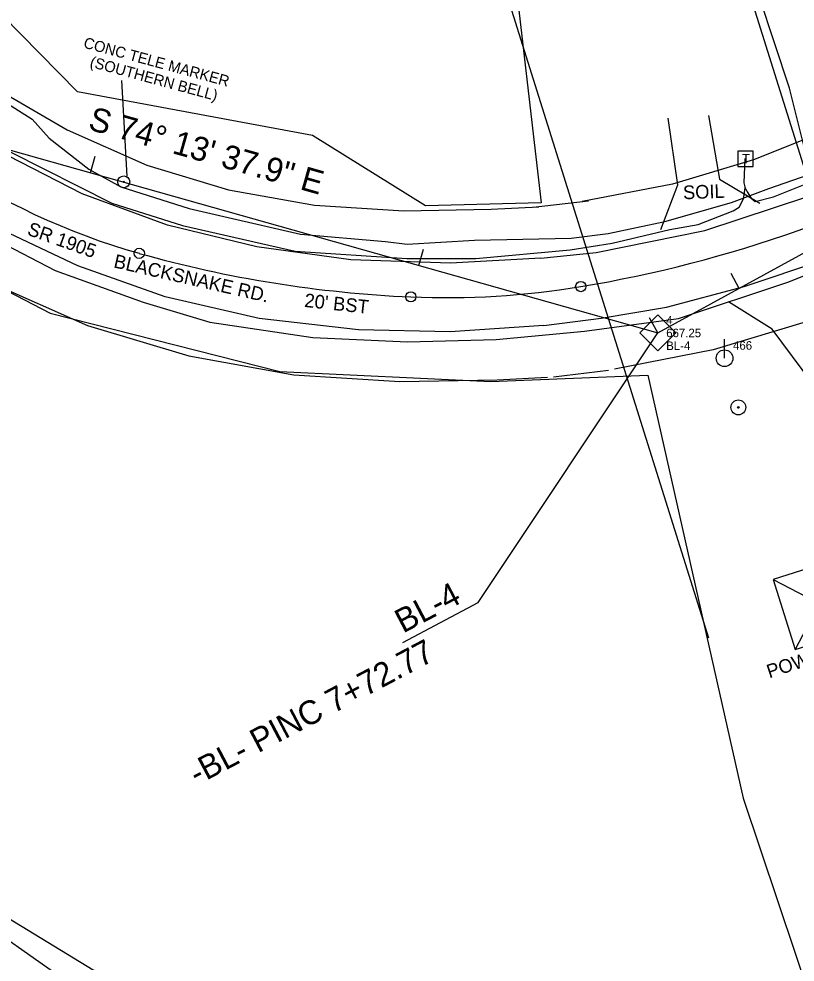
# Model space of a CAD drawing. Extents: x 1380524 to 1382335, y 594765 to 596944.
# Drawn here: x 1381338.3 to 1381565.9, y 595253.4 to 595529.8 of the extents above; entities that cross this region are included whole.
import ezdxf

# ---------------------------------------------------------------- set-up
doc = ezdxf.new("R2010")
doc.units = 0
for name, color, linetype in [('CTL Supplemental Horizontal and Vertical Cogo Comment', 7, 'Continuous'), ('CTL Supplemental Horizontal and Vertical Cogo Elevation', 7, 'Continuous'), ('DTM Contours Major', 7, 'Continuous'), ('Exist Horizontal Alignment', 7, 'Continuous'), ('Exist Horizontal Alignment Station Label', 7, 'Continuous'), ('Exist Horizontal Baseline Alignment', 7, 'Continuous'), ('Exist Horizontal Baseline Alignment Direction Label', 7, 'Continuous'), ('Exist Horizontal Baseline Alignment Station Label', 7, 'Continuous'), ('Exist Horizontal Baseline Alignment Tick small', 7, 'Continuous'), ('Exist Hydro Jurisdictional Stream or Body of Water', 7, 'Continuous'), ('Exist Other Culture Fence Line', 7, 'Continuous'), ('Exist Roads EOP', 7, 'Continuous'), ('Exist Roads EOP Other', 7, 'Continuous'), ('Exist Roads Soil', 7, 'Continuous'), ('Exist Utilities Gas UG Line SUE', 7, 'Continuous'), ('Exist Utilities Other Located Object Leader', 7, 'Continuous'), ('Exist Utilities Telephone Pedestal CELL', 7, 'Continuous'), ('Exist Utilities Telephone UG Cable', 7, 'Continuous'), ('Exist Vegetation Tree CELL', 7, 'Continuous'), ('Exist Vertical Profile Vertical Axis Label', 7, 'Continuous'), ('Prop Drainage Structure Pipe Elbow CELL', 7, 'Continuous'), ('Prop Earthen Structure Cut Ditch Special Detail CELL', 7, 'Continuous'), ('Prop Earthen Structure Cut Ditch Special Detail Label', 7, 'Continuous'), ('Prop Earthen Structure Ditch Flow Line', 7, 'Continuous'), ('Prop Horizontal Alignment Tick Large', 7, 'Continuous'), ('Prop Horizontal Alignment Tick Small', 7, 'Continuous'), ('Prop SS Cut Line', 7, 'Continuous'), ('Prop SS Fill Line', 7, 'Continuous'), ('Scratch_Level_6', 7, 'Continuous')]:
    doc.layers.add(name, color=color, linetype=linetype)

# ---------------------------------------------------------------- blocks, each defined once
blk = doc.blocks.new('EXIST UTILITIES OTHER LOCATED OBJECT')
at = {"layer": 'Prop Earthen Structure Cut Ditch Special Detail CELL'}
for radius in [0.0436, 0.0048]:
    blk.add_circle((0, 0), radius, dxfattribs=at)
blk = doc.blocks.new('EXIST UTILITIES POWER POLE')
at = {"layer": 'Exist Other Culture Fence Line'}
for q in [(0, 0.1125), (0, 0)]:
    blk.add_line((0, 0), q, dxfattribs=at)
blk.add_circle((0, 0), 0.049, dxfattribs=at)
blk = doc.blocks.new('EXIST UTILITIES TELEPHONE PEDESTAL')
at = {"layer": 'Exist Utilities Telephone Pedestal CELL'}
blk.add_line((0, 0), (0, 0), dxfattribs=at)
blk.add_lwpolyline([(-0.0545, -0.0565), (0.0574, -0.0565), (0.0574, 0.0554), (-0.0545, 0.0554), (-0.0545, -0.0565)], dxfattribs=at)
blk.add_text('T', height=0.0684, dxfattribs=at).set_placement((-0.0226, -0.0343))

msp = doc.modelspace()

# ---------------------------------------------------------------- linework, layer by layer
at = {"layer": 'DTM Contours Major'}
msp.add_lwpolyline([(1381559.46, 595365.58), (1381565.93, 595345.03), (1381586.48, 595351.5), (1381580.02, 595372.05), (1381559.46, 595365.58), (1381586.48, 595351.5), (1381580.02, 595372.05), (1381565.93, 595345.03)], dxfattribs=at)
at = {"layer": 'Exist Horizontal Alignment'}
for centre, radius, start, end in [((1381427.83, 595653.65), 200, 216.8315, 254.276), ((1381427.83, 595653.65), 200, 216.8315, 254.276), ((1381427.83, 595653.65), 200, 216.8315, 254.276), ((1381441.55, 595821.31), 375, 279.4361, 299.5612), ((1381441.55, 595821.31), 375, 279.4361, 299.5612), ((1381441.55, 595821.31), 375, 279.4361, 299.5612), ((1381468.48, 595798.03), 350, 254.276, 267.4994), ((1381468.48, 595798.03), 350, 254.276, 267.4994), ((1381468.48, 595798.03), 350, 254.276, 267.4994), ((1381463.68, 595688.14), 240, 267.4994, 279.4361), ((1381463.68, 595688.14), 240, 267.4994, 279.4361), ((1381463.68, 595688.14), 240, 267.4994, 279.4361)]:
    msp.add_arc(centre, radius, start, end, dxfattribs=at)
at = {"layer": 'Exist Horizontal Alignment Station Label'}
for centre in [(1381373.63, 595461.13), (1381503.03, 595451.39), (1381453.21, 595448.37)]:
    msp.add_circle(centre, 1.5, dxfattribs=at)
at = {"layer": 'Exist Horizontal Baseline Alignment'}
for p, q in [((1381525.59, 595437.8), (1381849.7, 595615.17)), ((1381263.09, 595511.95), (1381525.59, 595437.8))]:
    msp.add_line(p, q, dxfattribs=at)
at = {"layer": 'Exist Horizontal Baseline Alignment Station Label'}
for p, q in [((1381472.98, 595358.76), (1381525.59, 595437.8)), ((1381450.88, 595347.11), (1381472.98, 595358.76))]:
    msp.add_line(p, q, dxfattribs=at)
at = {"layer": 'Exist Horizontal Baseline Alignment Tick small'}
for p, q in [((1381359.33, 595484.76), (1381360.68, 595489.57)), ((1381455.56, 595457.58), (1381456.92, 595462.39)), ((1381549.48, 595450.87), (1381547.08, 595455.26)), ((1381525.59, 595437.8), (1381523.19, 595442.19))]:
    msp.add_line(p, q, dxfattribs=at)
at = {"layer": 'Exist Hydro Jurisdictional Stream or Body of Water'}
msp.add_lwpolyline([(1380985.02, 595366.88), (1381014.08, 595367.37), (1381042.38, 595363.3), (1381053.08, 595379.87), (1381083.61, 595386.57), (1381110.12, 595387.98), (1381133.86, 595373.94), (1381147.55, 595358.23), (1381189.33, 595341.18), (1381225.05, 595327.29), (1381256.58, 595311.26), (1381295.63, 595280.09), (1381330.47, 595263.19), (1381357.79, 595244.04), (1381403.48, 595232.23), (1381443.85, 595221.49), (1381471.36, 595213.42), (1381497.44, 595202.53)], dxfattribs=at)
at = {"layer": 'Exist Other Culture Fence Line'}
for q in [(1381545.19, 595436), (1381545.19, 595430.38)]:
    msp.add_line((1381545.19, 595430.38), q, dxfattribs=at)
msp.add_circle((1381545.19, 595430.38), 2.45, dxfattribs=at)
at = {"layer": 'Exist Roads EOP'}
for p, q in [((1381489.07, 595474.63), (1381505.26, 595476.56)), ((1381495, 595424.98), (1381511.19, 595426.92))]:
    msp.add_line(p, q, dxfattribs=at)
for points in [[(1381605.45, 595368.7), (1381418.22, 595965.25)], [(1381540.57, 595348.34), (1381353.34, 595944.89)], [(1381161.15, 595696), (1381164.06, 595686.12), (1381174.18, 595656.96), (1381185.71, 595627.95), (1381196.46, 595603.62), (1381208.77, 595578.34), (1381225.25, 595550.12), (1381243.05, 595524.53), (1381259.54, 595504.93), (1381280.57, 595484.48), (1381303.91, 595467.71), (1381329.76, 595452.68), (1381358.42, 595440), (1381388.14, 595431.06), (1381418.93, 595425.53), (1381449.98, 595423.57), (1381478.51, 595424.07), (1381493.32, 595424.85)], [(1381231.86, 595647.22), (1381241.81, 595624.69), (1381252.89, 595601.94), (1381267.43, 595577.05), (1381282.78, 595554.97), (1381296.18, 595539.04), (1381312.76, 595522.92), (1381331.13, 595509.71), (1381352.52, 595497.29), (1381375.81, 595486.97), (1381399.82, 595479.76), (1381424.98, 595475.23), (1381451.15, 595473.58), (1381476.8, 595474.04), (1381490.75, 595474.77)], [(1381633.23, 595526.86), (1381602.66, 595510.2), (1381576.4, 595497.62), (1381553.64, 595488.58), (1381529.89, 595481.4), (1381503.48, 595476.28)], [(1381657.14, 595482.97), (1381625.41, 595465.67), (1381596.39, 595451.78), (1381570.08, 595441.33), (1381541.87, 595432.81), (1381512.97, 595427.2)]]:
    msp.add_lwpolyline(points, dxfattribs=at)
at = {"layer": 'Exist Utilities Gas UG Line SUE'}
for p, q in [((1381564.26, 595509.53), (1381551.57, 595547.78)), ((1381571.71, 595479.42), (1381564.26, 595509.53))]:
    msp.add_line(p, q, dxfattribs=at)
at = {"layer": 'Exist Utilities Other Located Object Leader'}
msp.add_lwpolyline([(1381370.09, 595483.78), (1381368.47, 595511.8)], dxfattribs=at)
at = {"layer": 'Exist Utilities Telephone UG Cable'}
for p, q in [((1381324.33, 595511.79), (1381342.18, 595500.41)), ((1381342.18, 595500.41), (1381347.23, 595494.85)), ((1381347.23, 595494.85), (1381358.88, 595485.76)), ((1381335.74, 595490.85), (1381365.58, 595475.87)), ((1381550.94, 595481.8), (1381551.27, 595488.88)), ((1381358.88, 595485.76), (1381368.17, 595480.64)), ((1381558.21, 595480.11), (1381574.25, 595485.72)), ((1381551.27, 595480.59), (1381550.94, 595481.8)), ((1381559.54, 595477.68), (1381575.09, 595483.9)), ((1381368.17, 595480.64), (1381388.23, 595474.25)), ((1381547.2, 595476.01), (1381558.21, 595480.11)), ((1381550.74, 595477.08), (1381551.04, 595478.95)), ((1381551.04, 595478.95), (1381551.25, 595480.3)), ((1381551.25, 595480.3), (1381551.27, 595480.59)), ((1381551.25, 595480.3), (1381551.77, 595479.17)), ((1381551.77, 595479.17), (1381552.98, 595477.31)), ((1381527.68, 595470.49), (1381547.2, 595476.01)), ((1381549.5, 595474.7), (1381550.74, 595477.08)), ((1381552.98, 595477.31), (1381554.2, 595476.36)), ((1381554.2, 595476.36), (1381559.54, 595477.68)), ((1381365.58, 595475.87), (1381386.27, 595469.29)), ((1381388.23, 595474.25), (1381420.9, 595466.75)), ((1381537.47, 595469.61), (1381547.7, 595473.6)), ((1381547.7, 595473.6), (1381549.5, 595474.7)), ((1381511.03, 595466.91), (1381527.68, 595470.49)), ((1381324.11, 595469), (1381348.99, 595456.07)), ((1381386.27, 595469.29), (1381419.31, 595461.77)), ((1381512.25, 595464.09), (1381529.1, 595468.14)), ((1381529.1, 595468.14), (1381537.47, 595469.61)), ((1381420.9, 595466.75), (1381445.84, 595464.64)), ((1381452.13, 595463.78), (1381471.89, 595464.99)), ((1381471.89, 595464.99), (1381500.22, 595465.55)), ((1381500.22, 595465.55), (1381511.03, 595466.91)), ((1381445.84, 595464.64), (1381452.13, 595463.78)), ((1381499.91, 595462.15), (1381512.25, 595464.09)), ((1381419.31, 595461.77), (1381452.09, 595459.62)), ((1381452.09, 595459.62), (1381472.24, 595459.64)), ((1381472.24, 595459.64), (1381499.91, 595462.15)), ((1381564.06, 595452.79), (1381583.47, 595460.69)), ((1381348.99, 595456.07), (1381374.72, 595446.83)), ((1381531.69, 595442.05), (1381564.06, 595452.79)), ((1381374.72, 595446.83), (1381394.34, 595440.97)), ((1381394.34, 595440.97), (1381424.51, 595436.48)), ((1381504.1, 595438.32), (1381531.69, 595442.05)), ((1381478.25, 595435.91), (1381504.1, 595438.32)), ((1381424.51, 595436.48), (1381452.23, 595435.15)), ((1381452.23, 595435.15), (1381478.25, 595435.91))]:
    msp.add_line(p, q, dxfattribs=at)
at = {"layer": 'Prop Drainage Structure Pipe Elbow CELL'}
for points in [[(1381540.51, 595501.51), (1381543.66, 595482.82), (1381555.53, 595475.79)], [(1381526.48, 595468.13), (1381531.53, 595481.16), (1381528.67, 595500.75)], [(1381573.88, 595419.06), (1381559.15, 595438.88), (1381546.39, 595446.88)]]:
    msp.add_lwpolyline(points, dxfattribs=at)
at = {"layer": 'Prop Earthen Structure Cut Ditch Special Detail Label'}
for points in [[(1381311.01, 595552.25), (1381321.59, 595588.1), (1381354.11, 595565.54), (1381373.79, 595564.89), (1381382.69, 595595.08), (1381416.12, 595616.7), (1381418.47, 595677.64), (1381445.54, 595666.13), (1381483.46, 595545.08), (1381491.42, 595475.89), (1381457.51, 595475.03), (1381424.36, 595495.63), (1381355.51, 595508.44), (1381311.33, 595553.4)], [(1380970.1, 595427.87), (1381024.06, 595422.83), (1381114.96, 595446.92), (1381185.45, 595457.03), (1381261.8, 595488.06), (1381347.51, 595443.64), (1381414.83, 595426.48), (1381476.71, 595423.61), (1381522.74, 595425.41), (1381550.61, 595301.49), (1381576.12, 595225.45)], [(1381503.34, 595209.65), (1381437.89, 595231.26), (1381360.06, 595251.07), (1381310.4, 595281.34), (1381254.74, 595324.36), (1381199.97, 595347.63), (1381147.52, 595370.02), (1381108.16, 595398.49), (1381050.18, 595388.66), (1381033.41, 595371.94), (1380985.64, 595374.68)]]:
    msp.add_lwpolyline(points, dxfattribs=at)
at = {"layer": 'Prop Earthen Structure Ditch Flow Line'}
for p, q in [((1381491.33, 595459.68), (1381507.54, 595461.4)), ((1381492.25, 595440), (1381509.05, 595442.1))]:
    msp.add_line(p, q, dxfattribs=at)
for points in [[(1381491.33, 595459.68), (1381464.85, 595458.25), (1381435.67, 595459.27), (1381408.13, 595463.04), (1381381.89, 595469.34), (1381356.9, 595478.55), (1381331.5, 595491.59), (1381306.2, 595509.27), (1381284.93, 595529.02), (1381267.78, 595549.61), (1381247.25, 595580.06), (1381224.31, 595624.91), (1381211.16, 595655.93), (1381195.13, 595701.47), (1381187.72, 595727.78)], [(1381492.25, 595440), (1381464.79, 595438.13), (1381437.85, 595438.71), (1381408.74, 595442.02), (1381381.18, 595448.34), (1381355.66, 595457.45), (1381331.8, 595468.68), (1381308.83, 595482.8), (1381287.93, 595499.23), (1381269.66, 595517.22), (1381252.13, 595539.26), (1381236.19, 595562.85), (1381220.35, 595591.19), (1381206.28, 595620.98), (1381194.7, 595648.28), (1381177.83, 595693.24), (1381172.27, 595703.71), (1381163.83, 595709.25)], [(1381507.54, 595461.4), (1381539.44, 595467.79), (1381569.9, 595477.86), (1381604.03, 595493.18), (1381642.92, 595514.12)], [(1381509.05, 595442.1), (1381528.14, 595445.39), (1381550.94, 595451.4), (1381574.04, 595459.16), (1381596.63, 595468.8), (1381619.48, 595480.29), (1381651.75, 595498.4)]]:
    msp.add_lwpolyline(points, dxfattribs=at)
at = {"layer": 'Prop SS Cut Line'}
msp.add_line((1381525.59, 595437.8), (1381525.59, 595437.8), dxfattribs=at)
msp.add_lwpolyline([(1381520.38, 595437.82), (1381525.62, 595443.06), (1381530.87, 595437.81), (1381525.63, 595432.57)], close=True, dxfattribs=at)

# ---------------------------------------------------------------- block references
at = {"layer": 'Exist Other Culture Fence Line', "xscale": 50, "yscale": 50}
msp.add_blockref('EXIST UTILITIES POWER POLE', (1381545.19, 595430.38), dxfattribs=at)
at = {"layer": 'Exist Utilities Telephone Pedestal CELL', "xscale": 40, "yscale": 40}
msp.add_blockref('EXIST UTILITIES TELEPHONE PEDESTAL', (1381551.27, 595488.88), dxfattribs=at)
at = {"layer": 'Prop Earthen Structure Cut Ditch Special Detail CELL'}
for p, xscale, yscale in [((1381369.08, 595482.09), 40, 40), ((1381549.22, 595415.97), 50, 50)]:
    msp.add_blockref('EXIST UTILITIES OTHER LOCATED OBJECT', p, dxfattribs=dict(at, xscale=xscale, yscale=yscale))

# ---------------------------------------------------------------- texts
at = {"layer": 'CTL Supplemental Horizontal and Vertical Cogo Comment'}
msp.add_text('BL-4', height=2.5, dxfattribs=at).set_placement((1381528.09, 595432.8))
at = {"layer": 'CTL Supplemental Horizontal and Vertical Cogo Elevation'}
msp.add_text('667.25', height=2.5, dxfattribs=at).set_placement((1381528.09, 595436.55))
at = {"layer": 'Exist Horizontal Baseline Alignment Direction Label'}
msp.add_text('S 74%%d 13\' 37.9" E', height=7, rotation=344.2272, dxfattribs=at).set_placement((1381358.33, 595497.51))
at = {"layer": 'Exist Horizontal Baseline Alignment Station Label'}
msp.add_text('BL-4', height=7, rotation=27.7977, dxfattribs=at).set_placement((1381450.94, 595349.66))
at = {"layer": 'Exist Roads EOP Other'}
msp.add_text("20' BST", height=4, rotation=353.8056, dxfattribs=at).set_placement((1381421.88, 595445.44))
at = {"layer": 'Exist Roads Soil'}
msp.add_text('4', height=2.5, dxfattribs=at).set_placement((1381528.09, 595440.3))
at = {"layer": 'Exist Vegetation Tree CELL'}
msp.add_text('466', height=2.5, dxfattribs=at).set_placement((1381547.69, 595432.88))
msp.add_text('466', height=2.5, dxfattribs=at).set_placement((1381547.69, 595432.88))
at = {"layer": 'Exist Vertical Profile Vertical Axis Label'}
for s, rotation, p in [('SR 1905', 340.4323, (1381340.5, 595466.65)), ('BLACKSNAKE RD.', 347.0958, (1381365.89, 595457.04))]:
    msp.add_text(s, height=4, rotation=rotation, dxfattribs=at).set_placement(p)
at = {"layer": 'Prop Horizontal Alignment Tick Large'}
msp.add_text('SOIL', height=4, rotation=2.164, dxfattribs=at).set_placement((1381533.09, 595476.96))
at = {"layer": 'Prop Horizontal Alignment Tick Small'}
for s, p in [('CONC TELE MARKER', (1381357.06, 595521.46)), ('(SOUTHERN BELL)', (1381358.92, 595515.85))]:
    msp.add_text(s, height=3.2, rotation=344.8262, dxfattribs=at).set_placement(p)
at = {"layer": 'Prop SS Fill Line'}
msp.add_text('POWER TOWER', height=4, rotation=18.0203, dxfattribs=at).set_placement((1381558.31, 595336.55))
at = {"layer": 'Scratch_Level_6'}
msp.add_text('-BL- PINC 7+72.77 ', height=7, rotation=27.7977, dxfattribs=at).set_placement((1381390.52, 595305.11))

doc.saveas('drawing.dxf')
